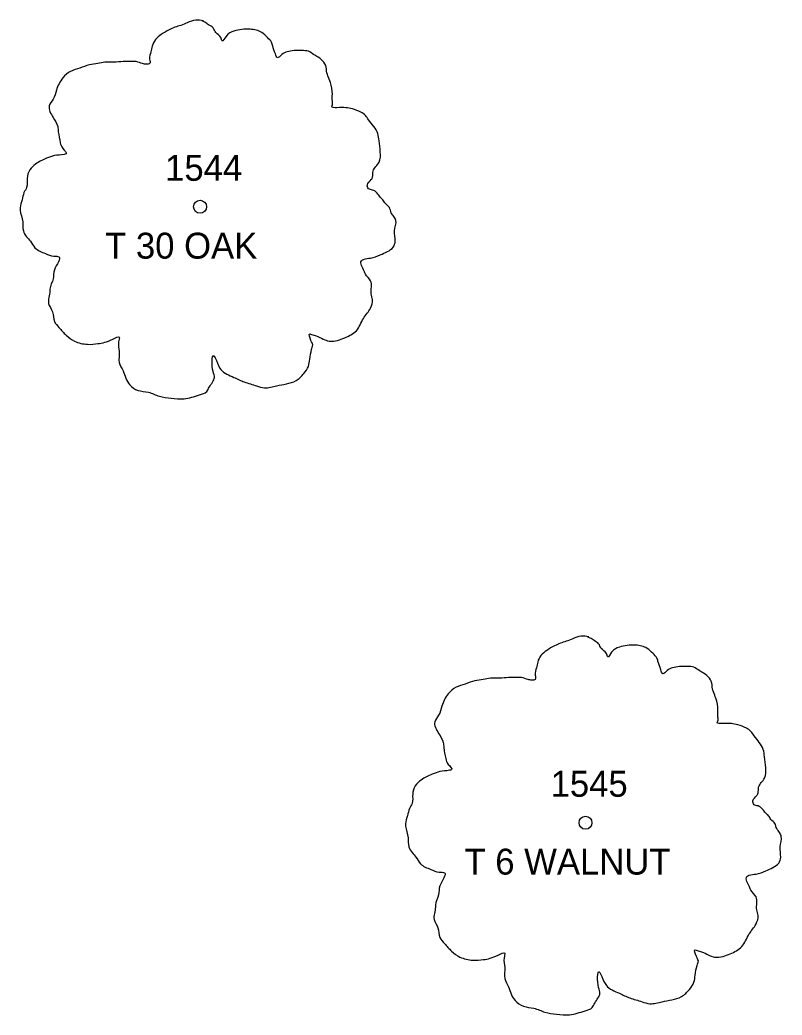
# Model space of a CAD drawing. Extents: x 1965304 to 1970247, y 1117014 to 1118201.
# Drawn here: x 1966511.04 to 1966540.44, y 1117424.72 to 1117463.08 of the extents above; entities that cross this region are included whole.
import ezdxf

# ---------------------------------------------------------------- set-up
doc = ezdxf.new("R2010")
doc.units = 0
doc.layers.add('RD_EX_VEG', color=7, linetype='Continuous')
doc.layers.add('RD_EX_VEG_txCode', color=7, linetype='Continuous')

msp = doc.modelspace()

# ---------------------------------------------------------------- linework, layer by layer
at = {"layer": 'RD_EX_VEG'}
for centre, radius in [((1966517.984, 1117455.877), 0.25), ((1966517.984, 1117455.877), 0.25), ((1966517.971, 1117455.858), 0.0001), ((1966517.971, 1117455.858), 0.0001), ((1966532.852, 1117432.136), 0.25), ((1966532.852, 1117432.136), 0.25), ((1966532.839, 1117432.118), 0.0001), ((1966532.839, 1117432.118), 0.0001)]:
    msp.add_circle(centre, radius, dxfattribs=at)
for points in [[(1966518.116, 1117463.044), (1966517.816, 1117463.069), (1966517.491, 1117462.969), (1966517.241, 1117462.869), (1966517.016, 1117462.794), (1966516.791, 1117462.694), (1966516.491, 1117462.52), (1966516.266, 1117462.32), (1966516.141, 1117462.07), (1966516.091, 1117461.845), (1966516.041, 1117461.57), (1966516.041, 1117461.395), (1966515.917, 1117461.37), (1966515.767, 1117461.395), (1966515.517, 1117461.47), (1966515.267, 1117461.47), (1966515.017, 1117461.47), (1966514.667, 1117461.445), (1966514.317, 1117461.445), (1966514.042, 1117461.395), (1966513.717, 1117461.345), (1966513.343, 1117461.22), (1966512.993, 1117461.095), (1966512.693, 1117460.845), (1966512.443, 1117460.371), (1966512.318, 1117460.021), (1966512.168, 1117459.771), (1966512.318, 1117459.321), (1966512.493, 1117458.971), (1966512.518, 1117458.771), (1966512.593, 1117458.346), (1966512.693, 1117458.122), (1966512.818, 1117457.922), (1966512.743, 1117457.897), (1966512.368, 1117457.847), (1966512.068, 1117457.747), (1966511.643, 1117457.522), (1966511.418, 1117457.297), (1966511.318, 1117456.972), (1966511.294, 1117456.622), (1966511.194, 1117456.422), (1966511.119, 1117456.147), (1966511.094, 1117456.072), (1966511.044, 1117455.748), (1966511.144, 1117455.298), (1966511.169, 1117454.948), (1966511.294, 1117454.723), (1966511.443, 1117454.548), (1966511.618, 1117454.298), (1966512.018, 1117454.073), (1966512.343, 1117453.973), (1966512.543, 1117453.948), (1966512.368, 1117453.449), (1966512.318, 1117453.099), (1966512.193, 1117452.699), (1966512.193, 1117452.624), (1966512.143, 1117452.149), (1966512.293, 1117451.824), (1966512.368, 1117451.449), (1966512.543, 1117451.225), (1966512.818, 1117450.925), (1966513.143, 1117450.7), (1966513.643, 1117450.575), (1966514.042, 1117450.6), (1966514.617, 1117450.775), (1966514.867, 1117450.85), (1966514.842, 1117450.675), (1966514.867, 1117450.3), (1966514.867, 1117449.875), (1966515.017, 1117449.55), (1966515.117, 1117449.275), (1966515.267, 1117449.025), (1966515.592, 1117448.801), (1966515.991, 1117448.726), (1966516.416, 1117448.576), (1966516.866, 1117448.501), (1966517.366, 1117448.476), (1966517.966, 1117448.626), (1966518.24, 1117448.751), (1966518.34, 1117448.926), (1966518.54, 1117449.3), (1966518.49, 1117449.525), (1966518.515, 1117450.125), (1966518.615, 1117449.95), (1966518.79, 1117449.6), (1966519.29, 1117449.3), (1966519.69, 1117449.125), (1966520.165, 1117448.975), (1966520.465, 1117448.901), (1966520.939, 1117448.975), (1966521.314, 1117449.05), (1966521.689, 1117449.175), (1966521.989, 1117449.45), (1966522.164, 1117449.725), (1966522.214, 1117450), (1966522.289, 1117450.375), (1966522.339, 1117450.55)], [(1966518.116, 1117463.044), (1966517.816, 1117463.069), (1966517.491, 1117462.969), (1966517.241, 1117462.869), (1966517.016, 1117462.794), (1966516.791, 1117462.694), (1966516.491, 1117462.52), (1966516.266, 1117462.32), (1966516.141, 1117462.07), (1966516.091, 1117461.845), (1966516.041, 1117461.57), (1966516.041, 1117461.395), (1966515.917, 1117461.37), (1966515.767, 1117461.395), (1966515.517, 1117461.47), (1966515.267, 1117461.47), (1966515.017, 1117461.47), (1966514.667, 1117461.445), (1966514.317, 1117461.445), (1966514.042, 1117461.395), (1966513.717, 1117461.345), (1966513.343, 1117461.22), (1966512.993, 1117461.095), (1966512.693, 1117460.845), (1966512.443, 1117460.371), (1966512.318, 1117460.021), (1966512.168, 1117459.771), (1966512.318, 1117459.321), (1966512.493, 1117458.971), (1966512.518, 1117458.771), (1966512.593, 1117458.346), (1966512.693, 1117458.122), (1966512.818, 1117457.922), (1966512.743, 1117457.897), (1966512.368, 1117457.847), (1966512.068, 1117457.747), (1966511.643, 1117457.522), (1966511.418, 1117457.297), (1966511.318, 1117456.972), (1966511.294, 1117456.622), (1966511.194, 1117456.422), (1966511.119, 1117456.147), (1966511.094, 1117456.072), (1966511.044, 1117455.748), (1966511.144, 1117455.298), (1966511.169, 1117454.948), (1966511.294, 1117454.723), (1966511.443, 1117454.548), (1966511.618, 1117454.298), (1966512.018, 1117454.073), (1966512.343, 1117453.973), (1966512.543, 1117453.948), (1966512.368, 1117453.449), (1966512.318, 1117453.099), (1966512.193, 1117452.699), (1966512.193, 1117452.624), (1966512.143, 1117452.149), (1966512.293, 1117451.824), (1966512.368, 1117451.449), (1966512.543, 1117451.225), (1966512.818, 1117450.925), (1966513.143, 1117450.7), (1966513.643, 1117450.575), (1966514.042, 1117450.6), (1966514.617, 1117450.775), (1966514.867, 1117450.85), (1966514.842, 1117450.675), (1966514.867, 1117450.3), (1966514.867, 1117449.875), (1966515.017, 1117449.55), (1966515.117, 1117449.275), (1966515.267, 1117449.025), (1966515.592, 1117448.801), (1966515.991, 1117448.726), (1966516.416, 1117448.576), (1966516.866, 1117448.501), (1966517.366, 1117448.476), (1966517.966, 1117448.626), (1966518.24, 1117448.751), (1966518.34, 1117448.926), (1966518.54, 1117449.3), (1966518.49, 1117449.525), (1966518.515, 1117450.125), (1966518.615, 1117449.95), (1966518.79, 1117449.6), (1966519.29, 1117449.3), (1966519.69, 1117449.125), (1966520.165, 1117448.975), (1966520.465, 1117448.901), (1966520.939, 1117448.975), (1966521.314, 1117449.05), (1966521.689, 1117449.175), (1966521.989, 1117449.45), (1966522.164, 1117449.725), (1966522.214, 1117450), (1966522.289, 1117450.375), (1966522.339, 1117450.55)], [(1966522.339, 1117450.55), (1966522.264, 1117450.725), (1966522.214, 1117450.975), (1966522.289, 1117450.95), (1966522.464, 1117450.9), (1966522.739, 1117450.775), (1966522.963, 1117450.7), (1966523.288, 1117450.725), (1966523.563, 1117450.825), (1966524.013, 1117451.1), (1966524.288, 1117451.574), (1966524.563, 1117451.974), (1966524.638, 1117452.299), (1966524.588, 1117452.524), (1966524.563, 1117453.024), (1966524.363, 1117453.274), (1966524.313, 1117453.399), (1966524.213, 1117453.798), (1966524.288, 1117453.848), (1966524.563, 1117453.898), (1966524.938, 1117454.023), (1966525.212, 1117454.148), (1966525.437, 1117454.323), (1966525.512, 1117454.548), (1966525.487, 1117454.948), (1966525.537, 1117455.348), (1966525.462, 1117455.498), (1966525.362, 1117455.648), (1966525.287, 1117455.848), (1966525.137, 1117455.997), (1966525.038, 1117456.147), (1966524.938, 1117456.247), (1966524.813, 1117456.397), (1966524.638, 1117456.522), (1966524.488, 1117456.572), (1966524.438, 1117456.722), (1966524.588, 1117456.922), (1966524.638, 1117457.022), (1966524.663, 1117457.247), (1966524.888, 1117457.597), (1966524.938, 1117457.997), (1966524.888, 1117458.421), (1966524.838, 1117458.696), (1966524.688, 1117458.971), (1966524.488, 1117459.221), (1966524.363, 1117459.396), (1966524.188, 1117459.521), (1966523.863, 1117459.646), (1966523.613, 1117459.696), (1966523.263, 1117459.696), (1966523.063, 1117459.746), (1966523.088, 1117459.796), (1966523.088, 1117459.946), (1966523.088, 1117460.221), (1966523.013, 1117460.67), (1966522.863, 1117461.17), (1966522.863, 1117461.195), (1966522.763, 1117461.445), (1966522.539, 1117461.645), (1966522.364, 1117461.745), (1966522.164, 1117461.87), (1966521.914, 1117461.895), (1966521.614, 1117461.895), (1966521.339, 1117461.845), (1966521.139, 1117461.745), (1966520.964, 1117461.62), (1966520.889, 1117461.77), (1966520.789, 1117462.07), (1966520.739, 1117462.22), (1966520.589, 1117462.395), (1966520.365, 1117462.595), (1966519.915, 1117462.719), (1966519.29, 1117462.645), (1966518.99, 1117462.445), (1966518.84, 1117462.27), (1966518.79, 1117462.395), (1966518.59, 1117462.595), (1966518.49, 1117462.769), (1966518.315, 1117462.894), (1966518.166, 1117462.994), (1966518.066, 1117463.044)], [(1966522.339, 1117450.55), (1966522.264, 1117450.725), (1966522.214, 1117450.975), (1966522.289, 1117450.95), (1966522.464, 1117450.9), (1966522.739, 1117450.775), (1966522.963, 1117450.7), (1966523.288, 1117450.725), (1966523.563, 1117450.825), (1966524.013, 1117451.1), (1966524.288, 1117451.574), (1966524.563, 1117451.974), (1966524.638, 1117452.299), (1966524.588, 1117452.524), (1966524.563, 1117453.024), (1966524.363, 1117453.274), (1966524.313, 1117453.399), (1966524.213, 1117453.798), (1966524.288, 1117453.848), (1966524.563, 1117453.898), (1966524.938, 1117454.023), (1966525.212, 1117454.148), (1966525.437, 1117454.323), (1966525.512, 1117454.548), (1966525.487, 1117454.948), (1966525.537, 1117455.348), (1966525.462, 1117455.498), (1966525.362, 1117455.648), (1966525.287, 1117455.848), (1966525.137, 1117455.997), (1966525.038, 1117456.147), (1966524.938, 1117456.247), (1966524.813, 1117456.397), (1966524.638, 1117456.522), (1966524.488, 1117456.572), (1966524.438, 1117456.722), (1966524.588, 1117456.922), (1966524.638, 1117457.022), (1966524.663, 1117457.247), (1966524.888, 1117457.597), (1966524.938, 1117457.997), (1966524.888, 1117458.421), (1966524.838, 1117458.696), (1966524.688, 1117458.971), (1966524.488, 1117459.221), (1966524.363, 1117459.396), (1966524.188, 1117459.521), (1966523.863, 1117459.646), (1966523.613, 1117459.696), (1966523.263, 1117459.696), (1966523.063, 1117459.746), (1966523.088, 1117459.796), (1966523.088, 1117459.946), (1966523.088, 1117460.221), (1966523.013, 1117460.67), (1966522.863, 1117461.17), (1966522.863, 1117461.195), (1966522.763, 1117461.445), (1966522.539, 1117461.645), (1966522.364, 1117461.745), (1966522.164, 1117461.87), (1966521.914, 1117461.895), (1966521.614, 1117461.895), (1966521.339, 1117461.845), (1966521.139, 1117461.745), (1966520.964, 1117461.62), (1966520.889, 1117461.77), (1966520.789, 1117462.07), (1966520.739, 1117462.22), (1966520.589, 1117462.395), (1966520.365, 1117462.595), (1966519.915, 1117462.719), (1966519.29, 1117462.645), (1966518.99, 1117462.445), (1966518.84, 1117462.27), (1966518.79, 1117462.395), (1966518.59, 1117462.595), (1966518.49, 1117462.769), (1966518.315, 1117462.894), (1966518.166, 1117462.994), (1966518.066, 1117463.044)], [(1966532.984, 1117439.304), (1966532.684, 1117439.329), (1966532.359, 1117439.229), (1966532.109, 1117439.129), (1966531.884, 1117439.054), (1966531.659, 1117438.954), (1966531.359, 1117438.779), (1966531.135, 1117438.579), (1966531.01, 1117438.329), (1966530.96, 1117438.104), (1966530.91, 1117437.829), (1966530.91, 1117437.654), (1966530.785, 1117437.629), (1966530.635, 1117437.654), (1966530.385, 1117437.729), (1966530.135, 1117437.729), (1966529.885, 1117437.729), (1966529.535, 1117437.704), (1966529.185, 1117437.704), (1966528.911, 1117437.654), (1966528.586, 1117437.604), (1966528.211, 1117437.479), (1966527.861, 1117437.354), (1966527.561, 1117437.105), (1966527.311, 1117436.63), (1966527.186, 1117436.28), (1966527.036, 1117436.03), (1966527.186, 1117435.58), (1966527.361, 1117435.23), (1966527.386, 1117435.03), (1966527.461, 1117434.606), (1966527.561, 1117434.381), (1966527.686, 1117434.181), (1966527.611, 1117434.156), (1966527.236, 1117434.106), (1966526.936, 1117434.006), (1966526.512, 1117433.781), (1966526.287, 1117433.556), (1966526.187, 1117433.231), (1966526.162, 1117432.881), (1966526.062, 1117432.682), (1966525.987, 1117432.407), (1966525.962, 1117432.332), (1966525.912, 1117432.007), (1966526.012, 1117431.557), (1966526.037, 1117431.207), (1966526.162, 1117430.982), (1966526.312, 1117430.807), (1966526.487, 1117430.557), (1966526.886, 1117430.333), (1966527.211, 1117430.233), (1966527.411, 1117430.208), (1966527.236, 1117429.708), (1966527.186, 1117429.358), (1966527.061, 1117428.958), (1966527.061, 1117428.883), (1966527.011, 1117428.408), (1966527.161, 1117428.083), (1966527.236, 1117427.709), (1966527.411, 1117427.484), (1966527.686, 1117427.184), (1966528.011, 1117426.959), (1966528.511, 1117426.834), (1966528.911, 1117426.859), (1966529.485, 1117427.034), (1966529.735, 1117427.109), (1966529.71, 1117426.934), (1966529.735, 1117426.559), (1966529.735, 1117426.134), (1966529.885, 1117425.81), (1966529.985, 1117425.535), (1966530.135, 1117425.285), (1966530.46, 1117425.06), (1966530.86, 1117424.985), (1966531.284, 1117424.835), (1966531.734, 1117424.76), (1966532.234, 1117424.735), (1966532.834, 1117424.885), (1966533.109, 1117425.01), (1966533.209, 1117425.185), (1966533.409, 1117425.56), (1966533.359, 1117425.785), (1966533.384, 1117426.384), (1966533.483, 1117426.209), (1966533.658, 1117425.859), (1966534.158, 1117425.56), (1966534.558, 1117425.385), (1966535.033, 1117425.235), (1966535.333, 1117425.16), (1966535.807, 1117425.235), (1966536.182, 1117425.31), (1966536.557, 1117425.435), (1966536.857, 1117425.71), (1966537.032, 1117425.984), (1966537.082, 1117426.259), (1966537.157, 1117426.634), (1966537.207, 1117426.809)], [(1966532.984, 1117439.304), (1966532.684, 1117439.329), (1966532.359, 1117439.229), (1966532.109, 1117439.129), (1966531.884, 1117439.054), (1966531.659, 1117438.954), (1966531.359, 1117438.779), (1966531.135, 1117438.579), (1966531.01, 1117438.329), (1966530.96, 1117438.104), (1966530.91, 1117437.829), (1966530.91, 1117437.654), (1966530.785, 1117437.629), (1966530.635, 1117437.654), (1966530.385, 1117437.729), (1966530.135, 1117437.729), (1966529.885, 1117437.729), (1966529.535, 1117437.704), (1966529.185, 1117437.704), (1966528.911, 1117437.654), (1966528.586, 1117437.604), (1966528.211, 1117437.479), (1966527.861, 1117437.354), (1966527.561, 1117437.105), (1966527.311, 1117436.63), (1966527.186, 1117436.28), (1966527.036, 1117436.03), (1966527.186, 1117435.58), (1966527.361, 1117435.23), (1966527.386, 1117435.03), (1966527.461, 1117434.606), (1966527.561, 1117434.381), (1966527.686, 1117434.181), (1966527.611, 1117434.156), (1966527.236, 1117434.106), (1966526.936, 1117434.006), (1966526.512, 1117433.781), (1966526.287, 1117433.556), (1966526.187, 1117433.231), (1966526.162, 1117432.881), (1966526.062, 1117432.682), (1966525.987, 1117432.407), (1966525.962, 1117432.332), (1966525.912, 1117432.007), (1966526.012, 1117431.557), (1966526.037, 1117431.207), (1966526.162, 1117430.982), (1966526.312, 1117430.807), (1966526.487, 1117430.557), (1966526.886, 1117430.333), (1966527.211, 1117430.233), (1966527.411, 1117430.208), (1966527.236, 1117429.708), (1966527.186, 1117429.358), (1966527.061, 1117428.958), (1966527.061, 1117428.883), (1966527.011, 1117428.408), (1966527.161, 1117428.083), (1966527.236, 1117427.709), (1966527.411, 1117427.484), (1966527.686, 1117427.184), (1966528.011, 1117426.959), (1966528.511, 1117426.834), (1966528.911, 1117426.859), (1966529.485, 1117427.034), (1966529.735, 1117427.109), (1966529.71, 1117426.934), (1966529.735, 1117426.559), (1966529.735, 1117426.134), (1966529.885, 1117425.81), (1966529.985, 1117425.535), (1966530.135, 1117425.285), (1966530.46, 1117425.06), (1966530.86, 1117424.985), (1966531.284, 1117424.835), (1966531.734, 1117424.76), (1966532.234, 1117424.735), (1966532.834, 1117424.885), (1966533.109, 1117425.01), (1966533.209, 1117425.185), (1966533.409, 1117425.56), (1966533.359, 1117425.785), (1966533.384, 1117426.384), (1966533.483, 1117426.209), (1966533.658, 1117425.859), (1966534.158, 1117425.56), (1966534.558, 1117425.385), (1966535.033, 1117425.235), (1966535.333, 1117425.16), (1966535.807, 1117425.235), (1966536.182, 1117425.31), (1966536.557, 1117425.435), (1966536.857, 1117425.71), (1966537.032, 1117425.984), (1966537.082, 1117426.259), (1966537.157, 1117426.634), (1966537.207, 1117426.809)], [(1966537.207, 1117426.809), (1966537.132, 1117426.984), (1966537.082, 1117427.234), (1966537.157, 1117427.209), (1966537.332, 1117427.159), (1966537.607, 1117427.034), (1966537.832, 1117426.959), (1966538.156, 1117426.984), (1966538.431, 1117427.084), (1966538.881, 1117427.359), (1966539.156, 1117427.834), (1966539.431, 1117428.233), (1966539.506, 1117428.558), (1966539.456, 1117428.783), (1966539.431, 1117429.283), (1966539.231, 1117429.533), (1966539.181, 1117429.658), (1966539.081, 1117430.058), (1966539.156, 1117430.108), (1966539.431, 1117430.158), (1966539.806, 1117430.283), (1966540.081, 1117430.407), (1966540.306, 1117430.582), (1966540.38, 1117430.807), (1966540.356, 1117431.207), (1966540.405, 1117431.607), (1966540.331, 1117431.757), (1966540.231, 1117431.907), (1966540.156, 1117432.107), (1966540.006, 1117432.257), (1966539.906, 1117432.407), (1966539.806, 1117432.507), (1966539.681, 1117432.657), (1966539.506, 1117432.781), (1966539.356, 1117432.831), (1966539.306, 1117432.981), (1966539.456, 1117433.181), (1966539.506, 1117433.281), (1966539.531, 1117433.506), (1966539.756, 1117433.856), (1966539.806, 1117434.256), (1966539.756, 1117434.681), (1966539.706, 1117434.956), (1966539.556, 1117435.23), (1966539.356, 1117435.48), (1966539.231, 1117435.655), (1966539.056, 1117435.78), (1966538.731, 1117435.905), (1966538.481, 1117435.955), (1966538.131, 1117435.955), (1966537.932, 1117436.005), (1966537.957, 1117436.055), (1966537.957, 1117436.205), (1966537.957, 1117436.48), (1966537.882, 1117436.93), (1966537.732, 1117437.429), (1966537.732, 1117437.454), (1966537.632, 1117437.704), (1966537.407, 1117437.904), (1966537.232, 1117438.004), (1966537.032, 1117438.129), (1966536.782, 1117438.154), (1966536.482, 1117438.154), (1966536.207, 1117438.104), (1966536.007, 1117438.004), (1966535.832, 1117437.879), (1966535.757, 1117438.029), (1966535.658, 1117438.329), (1966535.608, 1117438.479), (1966535.458, 1117438.654), (1966535.233, 1117438.854), (1966534.783, 1117438.979), (1966534.158, 1117438.904), (1966533.858, 1117438.704), (1966533.708, 1117438.529), (1966533.658, 1117438.654), (1966533.458, 1117438.854), (1966533.359, 1117439.029), (1966533.184, 1117439.154), (1966533.034, 1117439.254), (1966532.934, 1117439.304)], [(1966537.207, 1117426.809), (1966537.132, 1117426.984), (1966537.082, 1117427.234), (1966537.157, 1117427.209), (1966537.332, 1117427.159), (1966537.607, 1117427.034), (1966537.832, 1117426.959), (1966538.156, 1117426.984), (1966538.431, 1117427.084), (1966538.881, 1117427.359), (1966539.156, 1117427.834), (1966539.431, 1117428.233), (1966539.506, 1117428.558), (1966539.456, 1117428.783), (1966539.431, 1117429.283), (1966539.231, 1117429.533), (1966539.181, 1117429.658), (1966539.081, 1117430.058), (1966539.156, 1117430.108), (1966539.431, 1117430.158), (1966539.806, 1117430.283), (1966540.081, 1117430.407), (1966540.306, 1117430.582), (1966540.38, 1117430.807), (1966540.356, 1117431.207), (1966540.405, 1117431.607), (1966540.331, 1117431.757), (1966540.231, 1117431.907), (1966540.156, 1117432.107), (1966540.006, 1117432.257), (1966539.906, 1117432.407), (1966539.806, 1117432.507), (1966539.681, 1117432.657), (1966539.506, 1117432.781), (1966539.356, 1117432.831), (1966539.306, 1117432.981), (1966539.456, 1117433.181), (1966539.506, 1117433.281), (1966539.531, 1117433.506), (1966539.756, 1117433.856), (1966539.806, 1117434.256), (1966539.756, 1117434.681), (1966539.706, 1117434.956), (1966539.556, 1117435.23), (1966539.356, 1117435.48), (1966539.231, 1117435.655), (1966539.056, 1117435.78), (1966538.731, 1117435.905), (1966538.481, 1117435.955), (1966538.131, 1117435.955), (1966537.932, 1117436.005), (1966537.957, 1117436.055), (1966537.957, 1117436.205), (1966537.957, 1117436.48), (1966537.882, 1117436.93), (1966537.732, 1117437.429), (1966537.732, 1117437.454), (1966537.632, 1117437.704), (1966537.407, 1117437.904), (1966537.232, 1117438.004), (1966537.032, 1117438.129), (1966536.782, 1117438.154), (1966536.482, 1117438.154), (1966536.207, 1117438.104), (1966536.007, 1117438.004), (1966535.832, 1117437.879), (1966535.757, 1117438.029), (1966535.658, 1117438.329), (1966535.608, 1117438.479), (1966535.458, 1117438.654), (1966535.233, 1117438.854), (1966534.783, 1117438.979), (1966534.158, 1117438.904), (1966533.858, 1117438.704), (1966533.708, 1117438.529), (1966533.658, 1117438.654), (1966533.458, 1117438.854), (1966533.359, 1117439.029), (1966533.184, 1117439.154), (1966533.034, 1117439.254), (1966532.934, 1117439.304)]]:
    msp.add_spline(points, degree=3, dxfattribs=at)

# ---------------------------------------------------------------- texts
at = {"layer": 'RD_EX_VEG_txCode'}
for s, p in [('1544', (1966516.637, 1117456.877)), ('1544', (1966516.637, 1117456.877)), ('T 30 OAK', (1966514.322, 1117453.877)), ('T 30 OAK', (1966514.322, 1117453.877)), ('1545', (1966531.505, 1117433.136)), ('1545', (1966531.505, 1117433.136)), ('T 6 WALNUT', (1966528.183, 1117430.136)), ('T 6 WALNUT', (1966528.183, 1117430.136))]:
    msp.add_text(s, height=1, dxfattribs=at).set_placement(p)

doc.saveas('drawing.dxf')
